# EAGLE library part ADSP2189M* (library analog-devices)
DSP Microcomputer single-chip microcomputer optimized for digital signal processing (DSP)
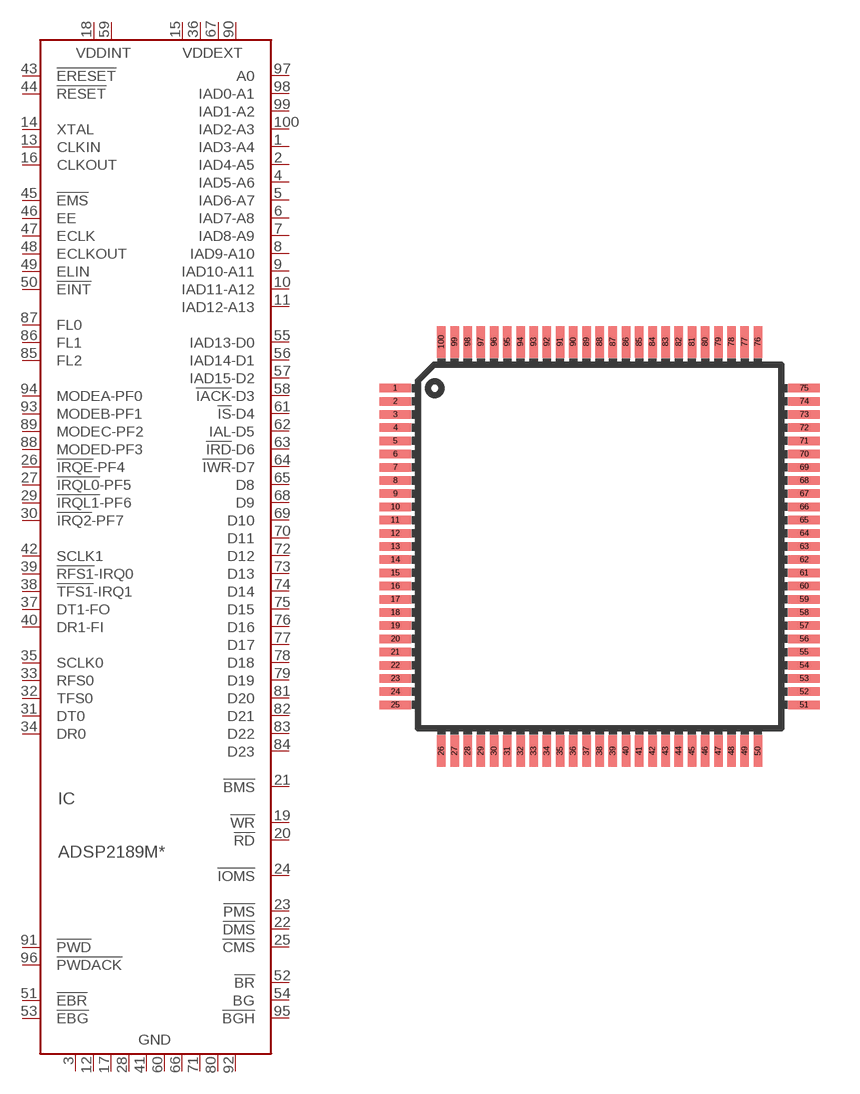
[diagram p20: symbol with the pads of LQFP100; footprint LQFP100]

Designator prefix IC

## ADSP2189MBST-266 (MF: ALTERA CORPORATION; MPN: ADSP-2189MBST-266; OC_FARNELL: 1465571; OC_NEWARK: 98B1516), ADSP2189MKST-300 (MF: ALTERA CORPORATION; MPN: ADSP-2189MKST-300; OC_FARNELL: 1465572; OC_NEWARK: 98B7141)  [LQFP100]
1  IAD3-A4  out
2  IAD4-A5  out
3  GND  pwr
4  IAD5-A6  out
5  IAD6-A7  out
6  IAD7-A8  out
7  IAD8-A9  out
8  IAD9-A10  out
9  IAD10-A11  out
10  IAD11-A12  out
11  IAD12-A13  out
12  GND  pwr
13  CLKIN  in
14  XTAL  in
15  VDDEXT  pwr
16  CLKOUT  out
17  GND  pwr
18  VDDINT  pwr
19  !WR  out
20  !RD  out
21  !BMS  out
22  !DMS  out
23  !PMS  out
24  !IOMS  out
25  !CMS  out
26  !IRQE!-PF4
27  !IRQL0!-PF5
28  GND  pwr
29  !IRQL1!-PF6
30  !IRQ2!-PF7
31  DT0  out
32  TFS0
33  RFS0
34  DR0  in
35  SCLK0
36  VDDEXT  pwr
37  DT1-FO  out
38  !TFS1!-IRQ1
39  !RFS1!-IRQ0
40  DR1-FI  in
41  GND  pwr
42  SCLK1
43  !ERESET  in
44  !RESET  in
45  !EMS
46  EE  in
47  ECLK  in
48  ECLKOUT  out
49  ELIN  in
50  !EINT  in
51  !EBR  in
52  !BR  in
53  !EBG  out
54  BG  out
55  IAD13-D0
56  IAD14-D1
57  IAD15-D2
58  !IACK!-D3
59  VDDINT  pwr
60  GND  pwr
61  !IS!-D4
62  IAL-D5
63  !IRD!-D6
64  !IWR!-D7
65  D8
66  GND  pwr
67  VDDEXT  pwr
68  D9
69  D10
70  D11
71  GND  pwr
72  D12
73  D13
74  D14
75  D15
76  D16
77  D17
78  D18
79  D19
80  GND  pwr
81  D20
82  D21
83  D22
84  D23
85  FL2  out
86  FL1  out
87  FL0  out
88  MODED-PF3
89  MODEC-PF2
90  VDDEXT  pwr
91  !PWD  in
92  GND  pwr
93  MODEB-PF1
94  MODEA-PF0
95  !BGH  out
96  !PWDACK  out
97  A0  out
98  IAD0-A1  out
99  IAD1-A2  out
100  IAD2-A3  out

## Footprint LQFP100 (pad centres in mm)
100-Lead Metric Thin Plastic Quad Flatpack
smd 1.2 x 0.32: 1 -7.75,6; 2 -7.75,5.5; 3 -7.75,5; 4 -7.75,4.5; 5 -7.75,4; 6 -7.75,3.5; 7 -7.75,3; 8 -7.75,2.5; 9 -7.75,2; 10 -7.75,1.5; 11 -7.75,1; 12 -7.75,0.5; 13 -7.75,0; 14 -7.75,-0.5; 15 -7.75,-1; 16 -7.75,-1.5; 17 -7.75,-2; 18 -7.75,-2.5; 19 -7.75,-3; 20 -7.75,-3.5; 21 -7.75,-4; 22 -7.75,-4.5; 23 -7.75,-5; 24 -7.75,-5.5; 25 -7.75,-6; 51 7.75,-6; 52 7.75,-5.5; 53 7.75,-5; 54 7.75,-4.5; 55 7.75,-4; 56 7.75,-3.5; 57 7.75,-3; 58 7.75,-2.5; 59 7.75,-2; 60 7.75,-1.5; 61 7.75,-1; 62 7.75,-0.5; 63 7.75,0; 64 7.75,0.5; 65 7.75,1; 66 7.75,1.5; 67 7.75,2; 68 7.75,2.5; 69 7.75,3; 70 7.75,3.5; 71 7.75,4; 72 7.75,4.5; 73 7.75,5; 74 7.75,5.5; 75 7.75,6
smd 0.32 x 1.2: 26 -6,-7.75; 27 -5.5,-7.75; 28 -5,-7.75; 29 -4.5,-7.75; 30 -4,-7.75; 31 -3.5,-7.75; 32 -3,-7.75; 33 -2.5,-7.75; 34 -2,-7.75; 35 -1.5,-7.75; 36 -1,-7.75; 37 -0.5,-7.75; 38 0,-7.75; 39 0.5,-7.75; 40 1,-7.75; 41 1.5,-7.75; 42 2,-7.75; 43 2.5,-7.75; 44 3,-7.75; 45 3.5,-7.75; 46 4,-7.75; 47 4.5,-7.75; 48 5,-7.75; 49 5.5,-7.75; 50 6,-7.75; 76 6,7.75; 77 5.5,7.75; 78 5,7.75; 79 4.5,7.75; 80 4,7.75; 81 3.5,7.75; 82 3,7.75; 83 2.5,7.75; 84 2,7.75; 85 1.5,7.75; 86 1,7.75; 87 0.5,7.75; 88 0,7.75; 89 -0.5,7.75; 90 -1,7.75; 91 -1.5,7.75; 92 -2,7.75; 93 -2.5,7.75; 94 -3,7.75; 95 -3.5,7.75; 96 -4,7.75; 97 -4.5,7.75; 98 -5,7.75; 99 -5.5,7.75; 100 -6,7.75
